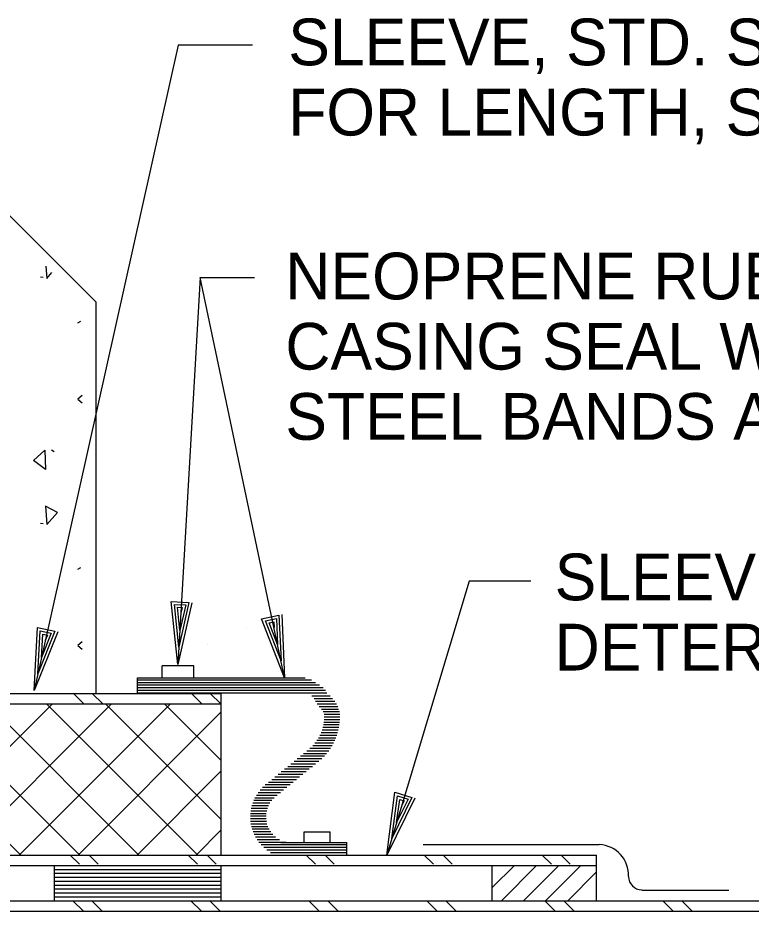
# Model space of a CAD drawing. Extents: x 22422.9 to 22498.9, y 22369.6 to 22415.
# Drawn here: x 22431.818 to 22434.748, y 22392.805 to 22396.373 of the extents above; entities that cross this region are included whole.
import ezdxf

# ---------------------------------------------------------------- set-up
doc = ezdxf.new("R2010")
doc.units = 0
for name, color, linetype in [('Level 1', 7, 'Continuous'), ('Level 2', 7, 'Continuous'), ('Level 4', 7, 'Continuous'), ('Level 44', 7, 'Continuous'), ('Level 7', 7, 'Continuous'), ('Level 8', 7, 'Continuous')]:
    doc.layers.add(name, color=color, linetype=linetype)

msp = doc.modelspace()

# ---------------------------------------------------------------- linework, layer by layer
at = {"layer": 'Level 1'}
for p, q in [((22432.7314, 22393.9395), (22432.7314, 22393.9395)), ((22432.5738, 22393.8708), (22432.5738, 22393.8708)), ((22432.3942, 22393.7364), (22432.3942, 22393.7841)), ((22432.5216, 22393.7841), (22432.3942, 22393.7841)), ((22432.5216, 22393.7364), (22432.5216, 22393.7841)), ((22431.1304, 22393.6748), (22432.6304, 22393.6748)), ((22432.6304, 22393.029), (22432.6304, 22393.6748)), ((22431.1304, 22393.6331), (22432.6304, 22393.6331)), ((22432.962, 22393.0786), (22432.962, 22393.1216)), ((22432.962, 22393.1216), (22433.0656, 22393.1216)), ((22433.0656, 22393.0786), (22433.0656, 22393.1216)), ((22431.1304, 22393.029), (22434.1304, 22393.029)), ((22431.1304, 22392.9873), (22434.1304, 22392.9873)), ((22433.7137, 22392.8989), (22433.8021, 22392.9873)), ((22433.7499, 22392.8467), (22433.8905, 22392.9873)), ((22433.8383, 22392.8467), (22433.9789, 22392.9873)), ((22433.9267, 22392.8467), (22434.0673, 22392.9873)), ((22431.9637, 22392.9717), (22432.6304, 22392.9717)), ((22431.9637, 22392.9561), (22432.6304, 22392.9561)), ((22434.0151, 22392.8467), (22434.1304, 22392.962)), ((22431.9637, 22392.9404), (22432.6304, 22392.9404)), ((22431.9637, 22392.9248), (22432.6304, 22392.9248)), ((22431.9637, 22392.9092), (22432.6304, 22392.9092)), ((22431.9637, 22392.8936), (22432.6304, 22392.8936)), ((22431.9637, 22392.8779), (22432.6304, 22392.8779)), ((22431.9637, 22392.8623), (22432.6304, 22392.8623))]:
    msp.add_line(p, q, dxfattribs=at)
at = {"layer": 'Level 2'}
for p, q in [((22432.8839, 22393.7367), (22432.5462, 22395.3361)), ((22432.5462, 22395.3361), (22432.7639, 22395.3361)), ((22432.2959, 22393.7364), (22432.9653, 22393.7364)), ((22432.2959, 22393.6748), (22432.2959, 22393.7364)), ((22432.8693, 22393.0786), (22433.1317, 22393.0786)), ((22433.1317, 22393.029), (22433.1317, 22393.0786)), ((22434.1304, 22392.8467), (22434.1304, 22393.029)), ((22431.9637, 22392.8467), (22431.9637, 22392.9873)), ((22432.6304, 22392.8467), (22432.6304, 22392.9873)), ((22433.7137, 22392.8467), (22433.7137, 22392.9873)), ((22431.1304, 22392.8467), (22437.7746, 22392.8467)), ((22431.1304, 22392.805), (22437.765, 22392.805))]:
    msp.add_line(p, q, dxfattribs=at)
for points in [[(22432.7552, 22396.263), (22432.4586, 22396.263), (22431.8825, 22393.6856)], [(22432.5462, 22395.3361), (22432.4575, 22393.7904)], [(22433.8676, 22394.1226), (22433.6218, 22394.1226), (22433.2922, 22393.029)], [(22432.513, 22394.0369), (22432.4575, 22393.7904), (22432.4305, 22394.0417), (22432.5011, 22394.0376), (22432.4615, 22393.8596), (22432.4432, 22394.0303), (22432.4885, 22394.0277), (22432.4653, 22393.9262), (22432.4559, 22394.0189), (22432.4746, 22394.0178), (22432.4693, 22393.9954)], [(22432.8728, 22393.9892), (22432.8839, 22393.7367), (22432.7919, 22393.9721), (22432.8611, 22393.9867), (22432.8696, 22393.8045), (22432.8072, 22393.9644), (22432.8515, 22393.9738), (22432.8558, 22393.8697), (22432.8224, 22393.9567), (22432.8407, 22393.9606), (22432.8415, 22393.9376)], [(22431.9772, 22393.92), (22431.8825, 22393.6856), (22431.8965, 22393.938), (22431.9655, 22393.9226), (22431.8976, 22393.7533), (22431.9072, 22393.9247), (22431.9514, 22393.9148), (22431.9121, 22393.8184), (22431.9179, 22393.9114), (22431.9361, 22393.9073), (22431.9273, 22393.886)], [(22432.2971, 22393.7291), (22432.9916, 22393.7291)], [(22432.2971, 22393.7187), (22433.0069, 22393.7187)], [(22432.2971, 22393.7082), (22433.0227, 22393.7082)], [(22432.2971, 22393.6978), (22433.0379, 22393.6978)], [(22432.2971, 22393.6874), (22433.0465, 22393.6874)], [(22432.2971, 22393.677), (22433.053, 22393.677)], [(22432.993, 22393.6644), (22433.0652, 22393.6644)], [(22433.002, 22393.654), (22433.0755, 22393.654)], [(22433.0078, 22393.6436), (22433.0846, 22393.6436)], [(22433.0142, 22393.6331), (22433.091, 22393.6331)], [(22433.0213, 22393.6227), (22433.0968, 22393.6227)], [(22433.031, 22393.6123), (22433.0994, 22393.6123)], [(22433.0382, 22393.6019), (22433.1032, 22393.6019)], [(22433.0413, 22393.5915), (22433.1039, 22393.5915)], [(22433.0403, 22393.5602), (22433.1032, 22393.5602)], [(22433.0413, 22393.5706), (22433.1039, 22393.5706)], [(22433.0417, 22393.5811), (22433.1042, 22393.5811)], [(22433.0295, 22393.5186), (22433.0955, 22393.5186)], [(22433.0333, 22393.529), (22433.0981, 22393.529)], [(22433.0363, 22393.5394), (22433.1003, 22393.5394)], [(22433.0387, 22393.5498), (22433.102, 22393.5498)], [(22433.0127, 22393.4873), (22433.0841, 22393.4873)], [(22433.0193, 22393.4977), (22433.0884, 22393.4977)], [(22433.0248, 22393.5081), (22433.0922, 22393.5081)], [(22432.9851, 22393.4561), (22433.067, 22393.4561)], [(22432.9959, 22393.4665), (22433.0734, 22393.4665)], [(22433.005, 22393.4769), (22433.0791, 22393.4769)], [(22432.9343, 22393.4144), (22433.0322, 22393.4144)], [(22432.947, 22393.4248), (22433.0426, 22393.4248)], [(22432.9598, 22393.4352), (22433.0517, 22393.4352)], [(22432.9726, 22393.4456), (22433.0598, 22393.4456)], [(22432.896, 22393.3831), (22432.9948, 22393.3831)], [(22432.9087, 22393.3936), (22433.0076, 22393.3936)], [(22432.9215, 22393.404), (22433.0203, 22393.404)], [(22432.8449, 22393.3415), (22432.9438, 22393.3415)], [(22432.8577, 22393.3519), (22432.9565, 22393.3519)], [(22432.8704, 22393.3623), (22432.9693, 22393.3623)], [(22432.8832, 22393.3727), (22432.982, 22393.3727)], [(22432.8066, 22393.3102), (22432.9055, 22393.3102)], [(22432.8194, 22393.3206), (22432.9182, 22393.3206)], [(22432.8321, 22393.3311), (22432.931, 22393.3311)], [(22432.7709, 22393.2686), (22432.8544, 22393.2686)], [(22432.7777, 22393.279), (22432.8672, 22393.279)], [(22432.7858, 22393.2894), (22432.8799, 22393.2894)], [(22432.7953, 22393.2998), (22432.8927, 22393.2998)], [(22433.4037, 22393.2558), (22433.2922, 22393.029), (22433.3245, 22393.2796), (22433.3922, 22393.2592), (22433.3122, 22393.0954), (22433.3342, 22393.2656), (22433.3776, 22393.2525), (22433.3314, 22393.1592), (22433.3439, 22393.2515), (22433.3618, 22393.2461), (22433.3514, 22393.2256)], [(22432.7562, 22393.2373), (22432.825, 22393.2373)], [(22432.7602, 22393.2477), (22432.8324, 22393.2477)], [(22432.7651, 22393.2581), (22432.842, 22393.2581)], [(22432.7486, 22393.2061), (22432.8121, 22393.2061)], [(22432.7504, 22393.2165), (22432.8151, 22393.2165)], [(22432.753, 22393.2269), (22432.8194, 22393.2269)], [(22432.7469, 22393.1852), (22432.8094, 22393.1852)], [(22432.7471, 22393.1748), (22432.8097, 22393.1748)], [(22432.7474, 22393.1956), (22432.8102, 22393.1956)], [(22432.7479, 22393.1644), (22432.811, 22393.1644)], [(22432.7494, 22393.154), (22432.8133, 22393.154)], [(22432.7515, 22393.1436), (22432.8169, 22393.1436)], [(22432.7544, 22393.1331), (22432.8218, 22393.1331)], [(22432.758, 22393.1227), (22432.8282, 22393.1227)], [(22432.7624, 22393.1123), (22432.8365, 22393.1123)], [(22432.7677, 22393.1019), (22432.8474, 22393.1019)], [(22432.7739, 22393.0915), (22432.8627, 22393.0915)], [(22432.7813, 22393.0811), (22432.8894, 22393.0811)], [(22432.7899, 22393.0706), (22433.1304, 22393.0706)], [(22432.8002, 22393.0602), (22433.1304, 22393.0602)], [(22432.8126, 22393.0498), (22433.1304, 22393.0498)], [(22432.828, 22393.0394), (22433.1304, 22393.0394)], [(22432.8484, 22393.029), (22433.1304, 22393.029)]]:
    msp.add_lwpolyline(points, dxfattribs=at)
at = {"layer": 'Level 44'}
for p, q in [((22431.9186, 22395.3358), (22431.9086, 22395.3366)), ((22432.0688, 22395.1596), (22432.0568, 22395.1536)), ((22431.9636, 22394.6393), (22431.9523, 22394.6461)), ((22431.9186, 22394.3521), (22431.9086, 22394.3528)), ((22432.0688, 22394.1758), (22432.0568, 22394.1698))]:
    msp.add_line(p, q, dxfattribs=at)
for points in [[(22431.9298, 22395.3809), (22431.9331, 22395.3323), (22431.954, 22395.3558)], [(22432.075, 22394.8646), (22432.0581, 22394.8498), (22432.075, 22394.8356)], [(22432.075, 22393.8808), (22432.0581, 22393.8661), (22432.075, 22393.8519)]]:
    msp.add_lwpolyline(points, dxfattribs=at)
for points in [[(22431.9281, 22394.5686), (22431.8801, 22394.6048), (22431.9261, 22394.6456)], [(22431.9331, 22394.3486), (22431.9758, 22394.3966), (22431.9281, 22394.4221)]]:
    msp.add_lwpolyline(points, close=True, dxfattribs=at)
at = {"layer": 'Level 7'}
for p, q in [((22432.1304, 22395.2373), (22431.6304, 22395.7373)), ((22432.1304, 22393.6748), (22432.1304, 22395.2373)), ((22433.4371, 22393.0706), (22434.1408, 22393.0706)), ((22434.3109, 22392.8883), (22434.6581, 22392.8883))]:
    msp.add_line(p, q, dxfattribs=at)
for centre, radius, start, end in [((22434.1356, 22392.9482), 0.1225, 357.5634, 87.5634), ((22434.3109, 22392.943), 0.0529, 180, 270)]:
    msp.add_arc(centre, radius, start, end, dxfattribs=at)
at = {"layer": 'Level 8'}
for p, q in [((22432.4615, 22393.8596), (22432.4615, 22393.8596)), ((22432.8696, 22393.8045), (22432.8696, 22393.8045)), ((22432.4575, 22393.7904), (22432.4575, 22393.7904)), ((22431.8976, 22393.7533), (22431.8976, 22393.7533)), ((22432.8839, 22393.7367), (22432.8839, 22393.7367)), ((22431.8825, 22393.6856), (22431.8825, 22393.6856)), ((22433.3122, 22393.0954), (22433.3122, 22393.0954)), ((22433.2922, 22393.029), (22433.2922, 22393.029))]:
    msp.add_line(p, q, dxfattribs=at)
for points in [[(22432.0815, 22393.6331), (22432.0398, 22393.6748)], [(22432.1569, 22393.6331), (22432.1153, 22393.6748)], [(22432.5529, 22393.6331), (22432.5113, 22393.6748)], [(22432.6283, 22393.6331), (22432.5867, 22393.6748)], [(22431.83, 22393.029), (22431.2258, 22393.6331)], [(22431.3516, 22393.029), (22431.9558, 22393.6331)], [(22432.0657, 22393.029), (22431.4615, 22393.6331)], [(22431.5873, 22393.029), (22432.1915, 22393.6331)], [(22432.3014, 22393.029), (22431.6972, 22393.6331)], [(22431.823, 22393.029), (22432.4272, 22393.6331)], [(22432.5371, 22393.029), (22431.9329, 22393.6331)], [(22432.6304, 22393.1714), (22432.1686, 22393.6331)], [(22432.6304, 22393.4071), (22432.4043, 22393.6331)], [(22432.0587, 22393.029), (22432.6304, 22393.6007)], [(22432.2944, 22393.029), (22432.6304, 22393.365)], [(22432.5301, 22393.029), (22432.6304, 22393.1293)], [(22432.064, 22392.9925), (22432.0275, 22393.029)], [(22432.1394, 22392.9925), (22432.1029, 22393.029)], [(22432.5354, 22392.9925), (22432.4989, 22393.029)], [(22432.6108, 22392.9925), (22432.5743, 22393.029)], [(22433.0068, 22392.9925), (22432.9703, 22393.029)], [(22433.0822, 22392.9925), (22433.0457, 22393.029)], [(22433.4782, 22392.9925), (22433.4417, 22393.029)], [(22433.5536, 22392.9925), (22433.5171, 22393.029)], [(22433.9496, 22392.9925), (22433.9131, 22393.029)], [(22434.025, 22392.9925), (22433.9885, 22393.029)], [(22432.0796, 22392.805), (22432.0379, 22392.8467)], [(22432.155, 22392.805), (22432.1133, 22392.8467)], [(22432.551, 22392.805), (22432.5093, 22392.8467)], [(22432.6264, 22392.805), (22432.5847, 22392.8467)], [(22433.0224, 22392.805), (22432.9807, 22392.8467)], [(22433.0978, 22392.805), (22433.0562, 22392.8467)], [(22433.4938, 22392.805), (22433.4521, 22392.8467)], [(22433.5692, 22392.805), (22433.5276, 22392.8467)], [(22433.9652, 22392.805), (22433.9235, 22392.8467)], [(22434.0406, 22392.805), (22433.999, 22392.8467)], [(22434.4366, 22392.805), (22434.3949, 22392.8467)], [(22434.512, 22392.805), (22434.4704, 22392.8467)]]:
    msp.add_lwpolyline(points, dxfattribs=at)

# ---------------------------------------------------------------- texts
at = {"layer": 'Level 4'}
for s, p in [('SLEEVE, STD. STEEL PIPE,', (22432.8983, 22396.1831)), ('FOR LENGTH, SEE SCHEDULE', (22432.8983, 22395.9027)), ('NEOPRENE RUBBER SLEEVE TYPE', (22432.8867, 22395.2482)), ('CASING SEAL WITH STAINLESS', (22432.8867, 22394.9678)), ('STEEL BANDS AND CLAMPS', (22432.8867, 22394.6874)), ('SLEEVE, STEEL PIPE SIZE', (22433.9627, 22394.0464)), ('DETERMINED BY LINK-SEAL', (22433.9627, 22393.766))]:
    msp.add_text(s, height=0.186667, dxfattribs=at).set_placement(p)

doc.saveas('drawing.dxf')
